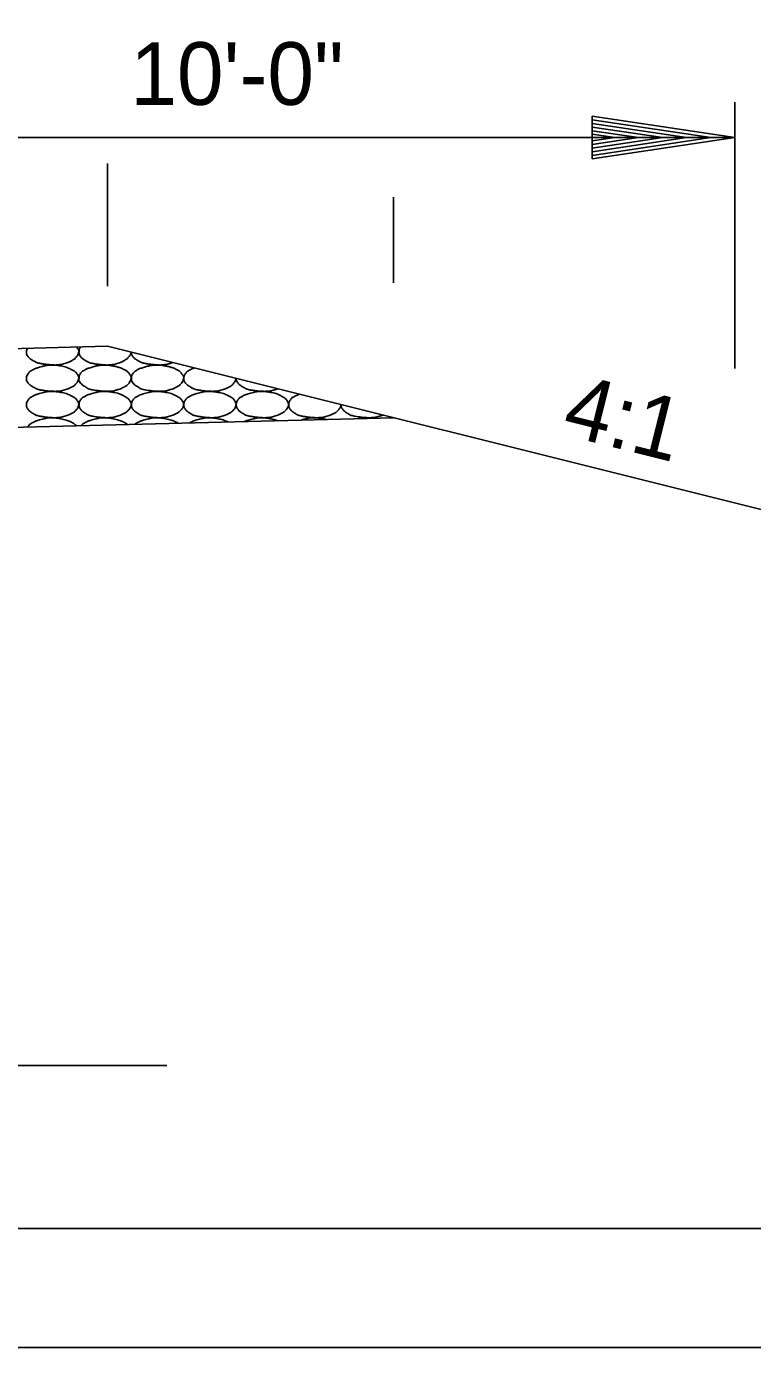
# Model space of a CAD drawing. Extents: x 1671357 to 13005564, y 567358 to 14261451.
# Drawn here: x 12758470.83 to 12758477.78, y 14259893.59 to 14259906.24 of the extents above; entities that cross this region are included whole.
import ezdxf

# ---------------------------------------------------------------- set-up
doc = ezdxf.new("R2010")
doc.units = 0
for name, color, linetype in [('Default', 7, 'Continuous'), ('R_Draft', 7, 'Continuous'), ('R_No Plot', 7, 'Continuous')]:
    doc.layers.add(name, color=color, linetype=linetype)

msp = doc.modelspace()

# ---------------------------------------------------------------- linework, layer by layer
at = {"layer": 'Default'}
for p, q in [((12758477.613, 14259902.964), (12758477.613, 14259905.515)), ((12758477.613, 14259905.177), (12758467.605, 14259905.177)), ((12758471.605, 14259903.752), (12758471.605, 14259904.927)), ((12758474.344, 14259903.784), (12758474.344, 14259904.606)), ((12758441.603, 14259902.429), (12758471.605, 14259903.178)), ((12758480.343, 14259900.993), (12758471.605, 14259903.178)), ((12758438.256, 14259901.592), (12758474.344, 14259902.493)), ((12758498.813, 14259894.727), (12758419.761, 14259894.727)), ((12758416.928, 14259893.587), (12758499.936, 14259893.587))]:
    msp.add_line(p, q, dxfattribs=at)
at = {"layer": 'R_Draft'}
for p, q in [((12758476.248, 14259905.381), (12758477.613, 14259905.177)), ((12758476.248, 14259905.381), (12758476.248, 14259904.972)), ((12758476.248, 14259905.347), (12758477.385, 14259905.177)), ((12758476.248, 14259905.313), (12758477.15, 14259905.177)), ((12758476.248, 14259905.278), (12758476.923, 14259905.177)), ((12758476.248, 14259905.243), (12758476.691, 14259905.177)), ((12758476.248, 14259905.209), (12758476.463, 14259905.177)), ((12758476.248, 14259904.972), (12758477.613, 14259905.177)), ((12758476.248, 14259905.11), (12758476.691, 14259905.177)), ((12758476.248, 14259905.041), (12758477.15, 14259905.177)), ((12758476.248, 14259905.006), (12758477.385, 14259905.177)), ((12758476.248, 14259905.075), (12758476.923, 14259905.177)), ((12758476.248, 14259905.145), (12758476.463, 14259905.177)), ((12758439.722, 14259896.29), (12758472.171, 14259896.29))]:
    msp.add_line(p, q, dxfattribs=at)
for points, degree in [([(12758471.308, 14259903.17), (12758471.312, 14259903.165), (12758471.316, 14259903.159), (12758471.327, 14259903.144), (12758471.33, 14259903.133), (12758471.325, 14259903.104), (12758471.315, 14259903.086), (12758471.291, 14259903.059), (12758471.282, 14259903.052), (12758471.25, 14259903.034), (12758471.23, 14259903.024), (12758471.18, 14259903.008), (12758471.151, 14259903.001), (12758471.108, 14259902.998), (12758471.093, 14259902.998), (12758471.056, 14259903.001), (12758471.034, 14259903.003), (12758470.988, 14259903.008), (12758470.964, 14259903.012), (12758470.921, 14259903.022), (12758470.904, 14259903.032), (12758470.866, 14259903.056), (12758470.85, 14259903.068), (12758470.829, 14259903.1), (12758470.828, 14259903.112), (12758470.829, 14259903.135), (12758470.831, 14259903.147), (12758470.837, 14259903.159)], 3), ([(12758471.83, 14259903.122), (12758471.827, 14259903.103), (12758471.817, 14259903.085), (12758471.793, 14259903.059), (12758471.784, 14259903.052), (12758471.752, 14259903.034), (12758471.733, 14259903.024), (12758471.682, 14259903.008), (12758471.654, 14259903.001), (12758471.61, 14259902.998), (12758471.595, 14259902.998), (12758471.559, 14259903.001), (12758471.537, 14259903.003), (12758471.49, 14259903.008), (12758471.467, 14259903.012), (12758471.423, 14259903.022), (12758471.406, 14259903.032), (12758471.369, 14259903.056), (12758471.353, 14259903.068), (12758471.331, 14259903.1), (12758471.33, 14259903.112), (12758471.332, 14259903.139), (12758471.335, 14259903.156), (12758471.347, 14259903.171), (12758471.347, 14259903.171), (12758471.347, 14259903.171)], 3), ([(12758472.228, 14259903.022), (12758472.223, 14259903.02), (12758472.218, 14259903.019), (12758472.185, 14259903.008), (12758472.156, 14259903.001), (12758472.112, 14259902.998), (12758472.098, 14259902.998), (12758472.061, 14259903.001), (12758472.039, 14259903.003), (12758471.993, 14259903.008), (12758471.969, 14259903.012), (12758471.925, 14259903.022), (12758471.909, 14259903.032), (12758471.871, 14259903.056), (12758471.855, 14259903.068), (12758471.834, 14259903.099), (12758471.833, 14259903.11), (12758471.833, 14259903.121)], 3), ([(12758471.078, 14259902.997), (12758471.108, 14259902.997), (12758471.137, 14259902.993), (12758471.202, 14259902.979), (12758471.235, 14259902.968), (12758471.29, 14259902.939), (12758471.306, 14259902.923), (12758471.327, 14259902.891), (12758471.33, 14259902.88), (12758471.325, 14259902.852), (12758471.315, 14259902.833), (12758471.291, 14259902.806), (12758471.282, 14259902.799), (12758471.25, 14259902.781), (12758471.23, 14259902.771), (12758471.18, 14259902.756), (12758471.151, 14259902.748), (12758471.108, 14259902.746), (12758471.093, 14259902.746), (12758471.056, 14259902.748), (12758471.034, 14259902.75), (12758470.988, 14259902.755), (12758470.964, 14259902.759), (12758470.921, 14259902.769), (12758470.904, 14259902.78), (12758470.866, 14259902.803), (12758470.85, 14259902.815), (12758470.829, 14259902.848), (12758470.828, 14259902.859), (12758470.829, 14259902.887), (12758470.833, 14259902.903), (12758470.856, 14259902.934), (12758470.869, 14259902.943), (12758470.897, 14259902.957), (12758470.91, 14259902.964), (12758470.944, 14259902.975), (12758470.964, 14259902.981), (12758470.997, 14259902.99), (12758471.009, 14259902.993), (12758471.041, 14259902.997), (12758471.06, 14259902.998), (12758471.078, 14259902.997)], 3), ([(12758471.581, 14259902.997), (12758471.61, 14259902.997), (12758471.639, 14259902.993), (12758471.669, 14259902.987), (12758471.704, 14259902.979), (12758471.737, 14259902.968), (12758471.771, 14259902.951), (12758471.793, 14259902.939), (12758471.808, 14259902.923), (12758471.823, 14259902.901), (12758471.829, 14259902.891), (12758471.832, 14259902.88), (12758471.831, 14259902.871), (12758471.827, 14259902.852), (12758471.817, 14259902.833), (12758471.803, 14259902.817), (12758471.793, 14259902.806), (12758471.784, 14259902.799), (12758471.773, 14259902.793), (12758471.752, 14259902.781), (12758471.733, 14259902.771), (12758471.711, 14259902.765), (12758471.682, 14259902.756), (12758471.654, 14259902.748), (12758471.625, 14259902.747), (12758471.61, 14259902.746), (12758471.595, 14259902.746), (12758471.581, 14259902.747), (12758471.559, 14259902.748), (12758471.537, 14259902.75), (12758471.515, 14259902.753), (12758471.49, 14259902.755), (12758471.467, 14259902.759), (12758471.443, 14259902.765), (12758471.423, 14259902.769), (12758471.406, 14259902.78), (12758471.389, 14259902.791), (12758471.369, 14259902.803), (12758471.353, 14259902.815), (12758471.339, 14259902.837), (12758471.331, 14259902.848), (12758471.33, 14259902.859), (12758471.331, 14259902.871), (12758471.332, 14259902.887), (12758471.335, 14259902.903), (12758471.347, 14259902.919), (12758471.358, 14259902.934), (12758471.371, 14259902.943), (12758471.387, 14259902.951), (12758471.4, 14259902.957), (12758471.413, 14259902.964), (12758471.427, 14259902.969), (12758471.446, 14259902.975), (12758471.466, 14259902.981), (12758471.487, 14259902.987), (12758471.499, 14259902.99), (12758471.512, 14259902.993), (12758471.525, 14259902.995), (12758471.543, 14259902.997), (12758471.562, 14259902.998), (12758471.581, 14259902.997)], 3), ([(12758472.083, 14259902.997), (12758472.112, 14259902.997), (12758472.142, 14259902.993), (12758472.171, 14259902.987), (12758472.207, 14259902.979), (12758472.24, 14259902.968), (12758472.273, 14259902.951), (12758472.295, 14259902.939), (12758472.31, 14259902.923), (12758472.325, 14259902.901), (12758472.331, 14259902.891), (12758472.335, 14259902.88), (12758472.333, 14259902.871), (12758472.33, 14259902.852), (12758472.32, 14259902.833), (12758472.305, 14259902.817), (12758472.296, 14259902.806), (12758472.286, 14259902.799), (12758472.275, 14259902.793), (12758472.255, 14259902.781), (12758472.235, 14259902.771), (12758472.213, 14259902.765), (12758472.185, 14259902.756), (12758472.156, 14259902.748), (12758472.127, 14259902.747), (12758472.112, 14259902.746), (12758472.098, 14259902.746), (12758472.083, 14259902.747), (12758472.061, 14259902.748), (12758472.039, 14259902.75), (12758472.017, 14259902.753), (12758471.993, 14259902.755), (12758471.969, 14259902.759), (12758471.945, 14259902.765), (12758471.925, 14259902.769), (12758471.909, 14259902.78), (12758471.891, 14259902.791), (12758471.871, 14259902.803), (12758471.855, 14259902.815), (12758471.841, 14259902.837), (12758471.834, 14259902.848), (12758471.832, 14259902.859), (12758471.833, 14259902.871), (12758471.834, 14259902.887), (12758471.837, 14259902.903), (12758471.849, 14259902.919), (12758471.861, 14259902.934), (12758471.874, 14259902.943), (12758471.889, 14259902.951), (12758471.902, 14259902.957), (12758471.915, 14259902.964), (12758471.929, 14259902.969), (12758471.949, 14259902.975), (12758471.969, 14259902.981), (12758471.989, 14259902.987), (12758472.002, 14259902.99), (12758472.014, 14259902.993), (12758472.027, 14259902.995), (12758472.046, 14259902.997), (12758472.064, 14259902.998), (12758472.083, 14259902.997)], 3), ([(12758472.835, 14259902.87), (12758472.832, 14259902.852), (12758472.822, 14259902.833), (12758472.798, 14259902.806), (12758472.789, 14259902.799), (12758472.757, 14259902.781), (12758472.737, 14259902.771), (12758472.687, 14259902.756), (12758472.659, 14259902.748), (12758472.615, 14259902.746), (12758472.6, 14259902.746), (12758472.563, 14259902.748), (12758472.541, 14259902.75), (12758472.495, 14259902.755), (12758472.471, 14259902.759), (12758472.428, 14259902.769), (12758472.411, 14259902.78), (12758472.374, 14259902.803), (12758472.357, 14259902.815), (12758472.336, 14259902.848), (12758472.335, 14259902.859), (12758472.336, 14259902.887), (12758472.34, 14259902.903), (12758472.363, 14259902.934), (12758472.376, 14259902.943), (12758472.405, 14259902.957), (12758472.418, 14259902.964), (12758472.433, 14259902.969), (12758472.435, 14259902.97), (12758472.436, 14259902.97)], 3), ([(12758473.235, 14259902.77), (12758473.229, 14259902.768), (12758473.224, 14259902.766), (12758473.189, 14259902.756), (12758473.161, 14259902.748), (12758473.117, 14259902.746), (12758473.103, 14259902.746), (12758473.066, 14259902.748), (12758473.044, 14259902.75), (12758472.998, 14259902.755), (12758472.974, 14259902.759), (12758472.93, 14259902.769), (12758472.913, 14259902.78), (12758472.876, 14259902.803), (12758472.86, 14259902.815), (12758472.839, 14259902.847), (12758472.837, 14259902.859), (12758472.838, 14259902.87)], 3), ([(12758471.078, 14259902.744), (12758471.108, 14259902.744), (12758471.137, 14259902.74), (12758471.202, 14259902.727), (12758471.235, 14259902.716), (12758471.29, 14259902.686), (12758471.306, 14259902.67), (12758471.327, 14259902.638), (12758471.33, 14259902.628), (12758471.325, 14259902.599), (12758471.315, 14259902.58), (12758471.291, 14259902.553), (12758471.282, 14259902.546), (12758471.25, 14259902.528), (12758471.23, 14259902.519), (12758471.18, 14259902.503), (12758471.151, 14259902.496), (12758471.108, 14259902.493), (12758471.093, 14259902.493), (12758471.056, 14259902.495), (12758471.034, 14259902.497), (12758470.988, 14259902.503), (12758470.964, 14259902.506), (12758470.921, 14259902.516), (12758470.904, 14259902.527), (12758470.866, 14259902.55), (12758470.85, 14259902.562), (12758470.829, 14259902.595), (12758470.828, 14259902.607), (12758470.829, 14259902.634), (12758470.833, 14259902.65), (12758470.856, 14259902.682), (12758470.869, 14259902.69), (12758470.897, 14259902.705), (12758470.91, 14259902.711), (12758470.944, 14259902.723), (12758470.964, 14259902.729), (12758470.997, 14259902.737), (12758471.009, 14259902.74), (12758471.041, 14259902.745), (12758471.06, 14259902.746), (12758471.078, 14259902.744)], 3), ([(12758471.581, 14259902.744), (12758471.61, 14259902.744), (12758471.639, 14259902.74), (12758471.704, 14259902.727), (12758471.737, 14259902.716), (12758471.793, 14259902.686), (12758471.808, 14259902.67), (12758471.829, 14259902.638), (12758471.832, 14259902.628), (12758471.827, 14259902.599), (12758471.817, 14259902.58), (12758471.793, 14259902.553), (12758471.784, 14259902.546), (12758471.752, 14259902.528), (12758471.733, 14259902.519), (12758471.682, 14259902.503), (12758471.654, 14259902.496), (12758471.61, 14259902.493), (12758471.595, 14259902.493), (12758471.559, 14259902.495), (12758471.537, 14259902.497), (12758471.49, 14259902.503), (12758471.467, 14259902.506), (12758471.423, 14259902.516), (12758471.406, 14259902.527), (12758471.369, 14259902.55), (12758471.353, 14259902.562), (12758471.331, 14259902.595), (12758471.33, 14259902.607), (12758471.332, 14259902.634), (12758471.335, 14259902.65), (12758471.358, 14259902.682), (12758471.371, 14259902.69), (12758471.4, 14259902.705), (12758471.413, 14259902.711), (12758471.446, 14259902.723), (12758471.466, 14259902.729), (12758471.499, 14259902.737), (12758471.512, 14259902.74), (12758471.543, 14259902.745), (12758471.562, 14259902.746), (12758471.581, 14259902.744)], 3), ([(12758472.083, 14259902.744), (12758472.112, 14259902.744), (12758472.142, 14259902.74), (12758472.207, 14259902.727), (12758472.24, 14259902.716), (12758472.295, 14259902.686), (12758472.31, 14259902.67), (12758472.331, 14259902.638), (12758472.335, 14259902.628), (12758472.33, 14259902.599), (12758472.32, 14259902.58), (12758472.296, 14259902.553), (12758472.286, 14259902.546), (12758472.255, 14259902.528), (12758472.235, 14259902.519), (12758472.185, 14259902.503), (12758472.156, 14259902.496), (12758472.112, 14259902.493), (12758472.098, 14259902.493), (12758472.061, 14259902.495), (12758472.039, 14259902.497), (12758471.993, 14259902.503), (12758471.969, 14259902.506), (12758471.925, 14259902.516), (12758471.909, 14259902.527), (12758471.871, 14259902.55), (12758471.855, 14259902.562), (12758471.834, 14259902.595), (12758471.832, 14259902.607), (12758471.834, 14259902.634), (12758471.837, 14259902.65), (12758471.861, 14259902.682), (12758471.874, 14259902.69), (12758471.902, 14259902.705), (12758471.915, 14259902.711), (12758471.949, 14259902.723), (12758471.969, 14259902.729), (12758472.002, 14259902.737), (12758472.014, 14259902.74), (12758472.046, 14259902.745), (12758472.064, 14259902.746), (12758472.083, 14259902.744)], 3), ([(12758472.585, 14259902.744), (12758472.615, 14259902.744), (12758472.644, 14259902.74), (12758472.709, 14259902.727), (12758472.742, 14259902.716), (12758472.798, 14259902.686), (12758472.813, 14259902.67), (12758472.834, 14259902.638), (12758472.837, 14259902.628), (12758472.832, 14259902.599), (12758472.822, 14259902.58), (12758472.798, 14259902.553), (12758472.789, 14259902.546), (12758472.757, 14259902.528), (12758472.737, 14259902.519), (12758472.687, 14259902.503), (12758472.659, 14259902.496), (12758472.615, 14259902.493), (12758472.6, 14259902.493), (12758472.563, 14259902.495), (12758472.541, 14259902.497), (12758472.495, 14259902.503), (12758472.471, 14259902.506), (12758472.428, 14259902.516), (12758472.411, 14259902.527), (12758472.374, 14259902.55), (12758472.357, 14259902.562), (12758472.336, 14259902.595), (12758472.335, 14259902.607), (12758472.336, 14259902.634), (12758472.34, 14259902.65), (12758472.363, 14259902.682), (12758472.376, 14259902.69), (12758472.405, 14259902.705), (12758472.418, 14259902.711), (12758472.451, 14259902.723), (12758472.471, 14259902.729), (12758472.504, 14259902.737), (12758472.517, 14259902.74), (12758472.548, 14259902.745), (12758472.567, 14259902.746), (12758472.585, 14259902.744)], 3), ([(12758473.088, 14259902.744), (12758473.117, 14259902.744), (12758473.147, 14259902.74), (12758473.212, 14259902.727), (12758473.245, 14259902.716), (12758473.3, 14259902.686), (12758473.315, 14259902.67), (12758473.336, 14259902.638), (12758473.34, 14259902.628), (12758473.335, 14259902.599), (12758473.325, 14259902.58), (12758473.301, 14259902.553), (12758473.291, 14259902.546), (12758473.26, 14259902.528), (12758473.24, 14259902.519), (12758473.189, 14259902.503), (12758473.161, 14259902.496), (12758473.117, 14259902.493), (12758473.103, 14259902.493), (12758473.066, 14259902.495), (12758473.044, 14259902.497), (12758472.998, 14259902.503), (12758472.974, 14259902.506), (12758472.93, 14259902.516), (12758472.913, 14259902.527), (12758472.876, 14259902.55), (12758472.86, 14259902.562), (12758472.839, 14259902.595), (12758472.837, 14259902.607), (12758472.839, 14259902.634), (12758472.842, 14259902.65), (12758472.866, 14259902.682), (12758472.878, 14259902.69), (12758472.907, 14259902.705), (12758472.92, 14259902.711), (12758472.954, 14259902.723), (12758472.974, 14259902.729), (12758473.006, 14259902.737), (12758473.019, 14259902.74), (12758473.05, 14259902.745), (12758473.069, 14259902.746), (12758473.088, 14259902.744)], 3), ([(12758473.84, 14259902.619), (12758473.84, 14259902.619), (12758473.84, 14259902.618), (12758473.837, 14259902.599), (12758473.827, 14259902.58), (12758473.803, 14259902.553), (12758473.794, 14259902.546), (12758473.762, 14259902.528), (12758473.742, 14259902.519), (12758473.692, 14259902.503), (12758473.664, 14259902.496), (12758473.62, 14259902.493), (12758473.605, 14259902.493), (12758473.568, 14259902.495), (12758473.546, 14259902.497), (12758473.5, 14259902.503), (12758473.476, 14259902.506), (12758473.433, 14259902.516), (12758473.416, 14259902.527), (12758473.378, 14259902.55), (12758473.362, 14259902.562), (12758473.341, 14259902.595), (12758473.34, 14259902.607), (12758473.341, 14259902.634), (12758473.345, 14259902.65), (12758473.368, 14259902.682), (12758473.381, 14259902.69), (12758473.409, 14259902.705), (12758473.422, 14259902.711), (12758473.439, 14259902.717), (12758473.441, 14259902.717), (12758473.443, 14259902.718)], 3), ([(12758474.242, 14259902.519), (12758474.235, 14259902.516), (12758474.229, 14259902.514), (12758474.194, 14259902.503), (12758474.166, 14259902.496), (12758474.122, 14259902.493), (12758474.107, 14259902.493), (12758474.071, 14259902.495), (12758474.049, 14259902.497), (12758474.002, 14259902.503), (12758473.979, 14259902.506), (12758473.935, 14259902.516), (12758473.918, 14259902.527), (12758473.881, 14259902.55), (12758473.865, 14259902.562), (12758473.843, 14259902.595), (12758473.842, 14259902.607), (12758473.843, 14259902.618), (12758473.843, 14259902.618), (12758473.843, 14259902.618)], 3), ([(12758470.839, 14259902.405), (12758470.84, 14259902.408), (12758470.842, 14259902.411), (12758470.856, 14259902.429), (12758470.869, 14259902.437), (12758470.897, 14259902.452), (12758470.91, 14259902.459), (12758470.944, 14259902.47), (12758470.964, 14259902.476), (12758470.997, 14259902.485), (12758471.009, 14259902.487), (12758471.041, 14259902.492), (12758471.06, 14259902.493), (12758471.078, 14259902.491)], 3), ([(12758471.078, 14259902.491), (12758471.108, 14259902.492), (12758471.137, 14259902.487), (12758471.202, 14259902.474), (12758471.235, 14259902.463), (12758471.282, 14259902.438), (12758471.294, 14259902.428), (12758471.304, 14259902.417)], 3), ([(12758471.351, 14259902.418), (12758471.361, 14259902.431), (12758471.373, 14259902.438), (12758471.4, 14259902.452), (12758471.413, 14259902.459), (12758471.446, 14259902.47), (12758471.466, 14259902.476), (12758471.499, 14259902.485), (12758471.512, 14259902.487), (12758471.543, 14259902.492), (12758471.562, 14259902.493), (12758471.581, 14259902.491)], 3), ([(12758471.581, 14259902.491), (12758471.61, 14259902.492), (12758471.639, 14259902.487), (12758471.704, 14259902.474), (12758471.737, 14259902.463), (12758471.779, 14259902.441), (12758471.787, 14259902.435), (12758471.794, 14259902.429)], 3), ([(12758471.866, 14259902.431), (12758471.873, 14259902.437), (12758471.881, 14259902.441), (12758471.902, 14259902.452), (12758471.915, 14259902.459), (12758471.949, 14259902.47), (12758471.969, 14259902.476), (12758472.002, 14259902.485), (12758472.014, 14259902.487), (12758472.046, 14259902.492), (12758472.064, 14259902.493), (12758472.083, 14259902.491)], 3), ([(12758472.083, 14259902.491), (12758472.112, 14259902.492), (12758472.142, 14259902.487), (12758472.207, 14259902.474), (12758472.24, 14259902.463), (12758472.275, 14259902.444), (12758472.278, 14259902.443), (12758472.28, 14259902.441)], 3), ([(12758472.389, 14259902.444), (12758472.39, 14259902.445), (12758472.391, 14259902.445), (12758472.405, 14259902.452), (12758472.418, 14259902.459), (12758472.451, 14259902.47), (12758472.471, 14259902.476), (12758472.504, 14259902.485), (12758472.517, 14259902.487), (12758472.548, 14259902.492), (12758472.567, 14259902.493), (12758472.585, 14259902.491)], 3), ([(12758472.585, 14259902.491), (12758472.615, 14259902.492), (12758472.644, 14259902.487), (12758472.704, 14259902.475), (12758472.732, 14259902.467), (12758472.76, 14259902.453)], 3), ([(12758472.918, 14259902.457), (12758472.923, 14259902.46), (12758472.929, 14259902.462), (12758472.954, 14259902.47), (12758472.974, 14259902.476), (12758473.006, 14259902.485), (12758473.019, 14259902.487), (12758473.05, 14259902.492), (12758473.069, 14259902.493), (12758473.088, 14259902.491)], 3), ([(12758473.088, 14259902.491), (12758473.117, 14259902.492), (12758473.147, 14259902.487), (12758473.196, 14259902.477), (12758473.215, 14259902.472), (12758473.234, 14259902.465)], 3), ([(12758473.459, 14259902.471), (12758473.472, 14259902.475), (12758473.484, 14259902.478), (12758473.509, 14259902.485), (12758473.521, 14259902.487), (12758473.553, 14259902.492), (12758473.572, 14259902.493), (12758473.59, 14259902.491)], 3), ([(12758473.59, 14259902.491), (12758473.62, 14259902.492), (12758473.649, 14259902.487), (12758473.685, 14259902.48), (12758473.692, 14259902.478), (12758473.698, 14259902.477)], 3), ([(12758474.012, 14259902.485), (12758474.02, 14259902.486), (12758474.028, 14259902.488), (12758474.055, 14259902.492), (12758474.074, 14259902.493), (12758474.093, 14259902.491)], 3), ([(12758474.093, 14259902.491), (12758474.109, 14259902.492), (12758474.126, 14259902.49), (12758474.143, 14259902.488)], 2)]:
    msp.add_open_spline(points, degree=degree, dxfattribs=at)
at = {"layer": 'R_No Plot'}
msp.add_lwpolyline([(12758416.928, 14259946.667), (12758499.936, 14259946.667), (12758499.936, 14259893.587), (12758416.928, 14259893.587)], close=True, dxfattribs=at)

# ---------------------------------------------------------------- texts
at = {"layer": 'R_Draft'}
msp.add_text('10\'-0"', height=0.6001, dxfattribs=at).set_placement((12758471.823, 14259905.49))
msp.add_text('4:1', height=0.6001, rotation=345.96, dxfattribs=at).set_placement((12758475.941, 14259902.337))

doc.saveas('drawing.dxf')
